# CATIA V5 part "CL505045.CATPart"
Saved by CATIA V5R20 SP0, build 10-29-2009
Part number: CL505045
Bounding box of the stored display mesh (mm): x -22.5 to 22.5, y -41 to 0, z -15 to 15
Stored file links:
  C:\Users\Raffaele\Desktop\3D X SITO CF\BOLEX\17-CENTERER REF 505\CL505045.CATPart
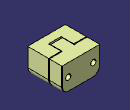
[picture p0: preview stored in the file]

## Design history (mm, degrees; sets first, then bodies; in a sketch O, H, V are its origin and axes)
Set1
  DatumSurface1 to DatumSurface75 "MANIFOLD_SOLID_BREP #2047"
  DatumSurface76 to DatumSurface79 "MANIFOLD_SOLID_BREP #2135"
  DatumSurface80 to DatumSurface83 "MANIFOLD_SOLID_BREP #2223"
  DatumSurface84 to DatumSurface87 "MANIFOLD_SOLID_BREP #2311"
  DatumSurface88 to DatumSurface91 "MANIFOLD_SOLID_BREP #2399"
  DatumSurface92 to DatumSurface95 "MANIFOLD_SOLID_BREP #2487"
  DatumSurface96 to DatumSurface99 "MANIFOLD_SOLID_BREP #2575"
  DatumSurface100 to DatumSurface103 "MANIFOLD_SOLID_BREP #2663"
  DatumSurface104 to DatumSurface107 "MANIFOLD_SOLID_BREP #2751"
  DatumSurface108 to DatumSurface111 "MANIFOLD_SOLID_BREP #2839"
  DatumSurface112 to DatumSurface115 "MANIFOLD_SOLID_BREP #2927"
  DatumSurface116 to DatumSurface119 "MANIFOLD_SOLID_BREP #3015"
  DatumSurface120 to DatumSurface123 "MANIFOLD_SOLID_BREP #3103"
  DatumSurface124 to DatumSurface152 "MANIFOLD_SOLID_BREP #3995"
Body1 (main body)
